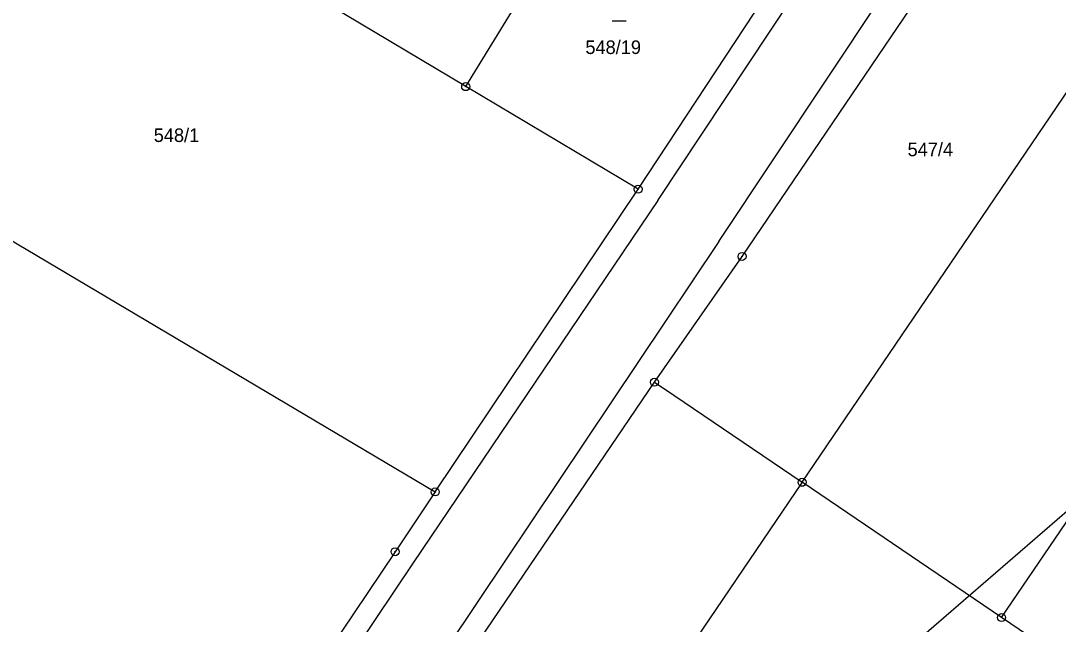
# Model space of a CAD drawing. Extents: x -758582 to -751794, y -998770 to -994350.
# Drawn here: x -754377.8 to -754248.1, y -997140.7 to -997065.3 of the extents above; entities that cross this region are included whole.
import ezdxf

# ---------------------------------------------------------------- set-up
doc = ezdxf.new("R2010")
doc.units = 0
for name, color, linetype in [('Hranice parcel', 7, 'Continuous'), ('Parcelní čísla', 7, 'Continuous'), ('Poz předměty', 7, 'Continuous'), ('Vnitřní kresba', 7, 'Continuous'), ('Značky bodu BP', 7, 'Continuous'), ('Značky kultur', 7, 'Continuous')]:
    doc.layers.add(name, color=color, linetype=linetype)

msp = doc.modelspace()

# ---------------------------------------------------------------- linework, layer by layer
at = {"layer": 'Hranice parcel'}
for p, q in [((-754280.16, -997123), (-754225.65, -997042.61)), ((-754322.2, -997073.53), (-754306.17, -997047.33)), ((-754255.21, -997139.91), (-754201.32, -997060.42)), ((-754300.65, -997086.35), (-754284.03, -997061.1)), ((-754322.2, -997073.53), (-754339.18, -997063.38)), ((-754300.65, -997086.35), (-754322.2, -997073.53)), ((-754409.22, -997074.84), (-754326.01, -997124.2)), ((-754326.01, -997124.2), (-754300.65, -997086.35)), ((-754334.7, -997163.7), (-754298.61, -997110.48)), ((-754280.16, -997123), (-754316.24, -997176.22)), ((-754255.21, -997139.91), (-754280.16, -997123)), ((-754217.67, -997165.37), (-754255.21, -997139.91))]:
    msp.add_line(p, q, dxfattribs=at)
for points in [[(-754298.61, -997110.48), (-754287.65, -997094.76), (-754247.23, -997035.13), (-754244.34, -997029.93)], [(-754298.61, -997110.48), (-754296.2, -997112.11), (-754280.16, -997123)], [(-754326.01, -997124.2), (-754331.02, -997131.68), (-754351.33, -997161.95)]]:
    msp.add_lwpolyline(points, dxfattribs=at)
at = {"layer": 'Poz předměty'}
msp.add_line((-754266.75, -997143.66), (-754228.01, -997110.07), dxfattribs=at)
at = {"layer": 'Vnitřní kresba'}
for p, q in [((-754298.18, -997087.75), (-754258.56, -997028)), ((-754290.57, -997092.9), (-754250.41, -997032.48)), ((-754298.18, -997087.75), (-754328.75, -997133.06)), ((-754290.57, -997092.9), (-754320.7, -997137.9)), ((-754328.75, -997133.06), (-754360.05, -997179.72)), ((-754320.7, -997137.9), (-754351.53, -997183.9))]:
    msp.add_line(p, q, dxfattribs=at)
at = {"layer": 'Značky bodu BP'}
for centre, radius in [((-754322.2, -997073.53), 0.5), ((-754322.2, -997073.53), 0.0303), ((-754300.65, -997086.35), 0.5), ((-754300.65, -997086.35), 0.0303), ((-754287.65, -997094.76), 0.5), ((-754287.65, -997094.76), 0.0303), ((-754298.61, -997110.48), 0.5), ((-754298.61, -997110.48), 0.0303), ((-754280.16, -997123), 0.5), ((-754280.16, -997123), 0.0303), ((-754326.01, -997124.2), 0.5), ((-754326.01, -997124.2), 0.0303), ((-754331.02, -997131.68), 0.5), ((-754331.02, -997131.68), 0.0303), ((-754255.21, -997139.91), 0.5), ((-754255.21, -997139.91), 0.0303)]:
    msp.add_circle(centre, radius, dxfattribs=at)
at = {"layer": 'Značky kultur'}
msp.add_line((-754303.91, -997065.29), (-754302.16, -997065.29), dxfattribs=at)

# ---------------------------------------------------------------- texts
at = {"layer": 'Parcelní čísla'}
for s, p in [('548/19', (-754307.24, -997069.45)), ('548/1', (-754361.19, -997080.45)), ('547/4', (-754266.97, -997082.23))]:
    msp.add_text(s, height=1.7, dxfattribs=at).set_placement(p)

doc.saveas('drawing.dxf')
